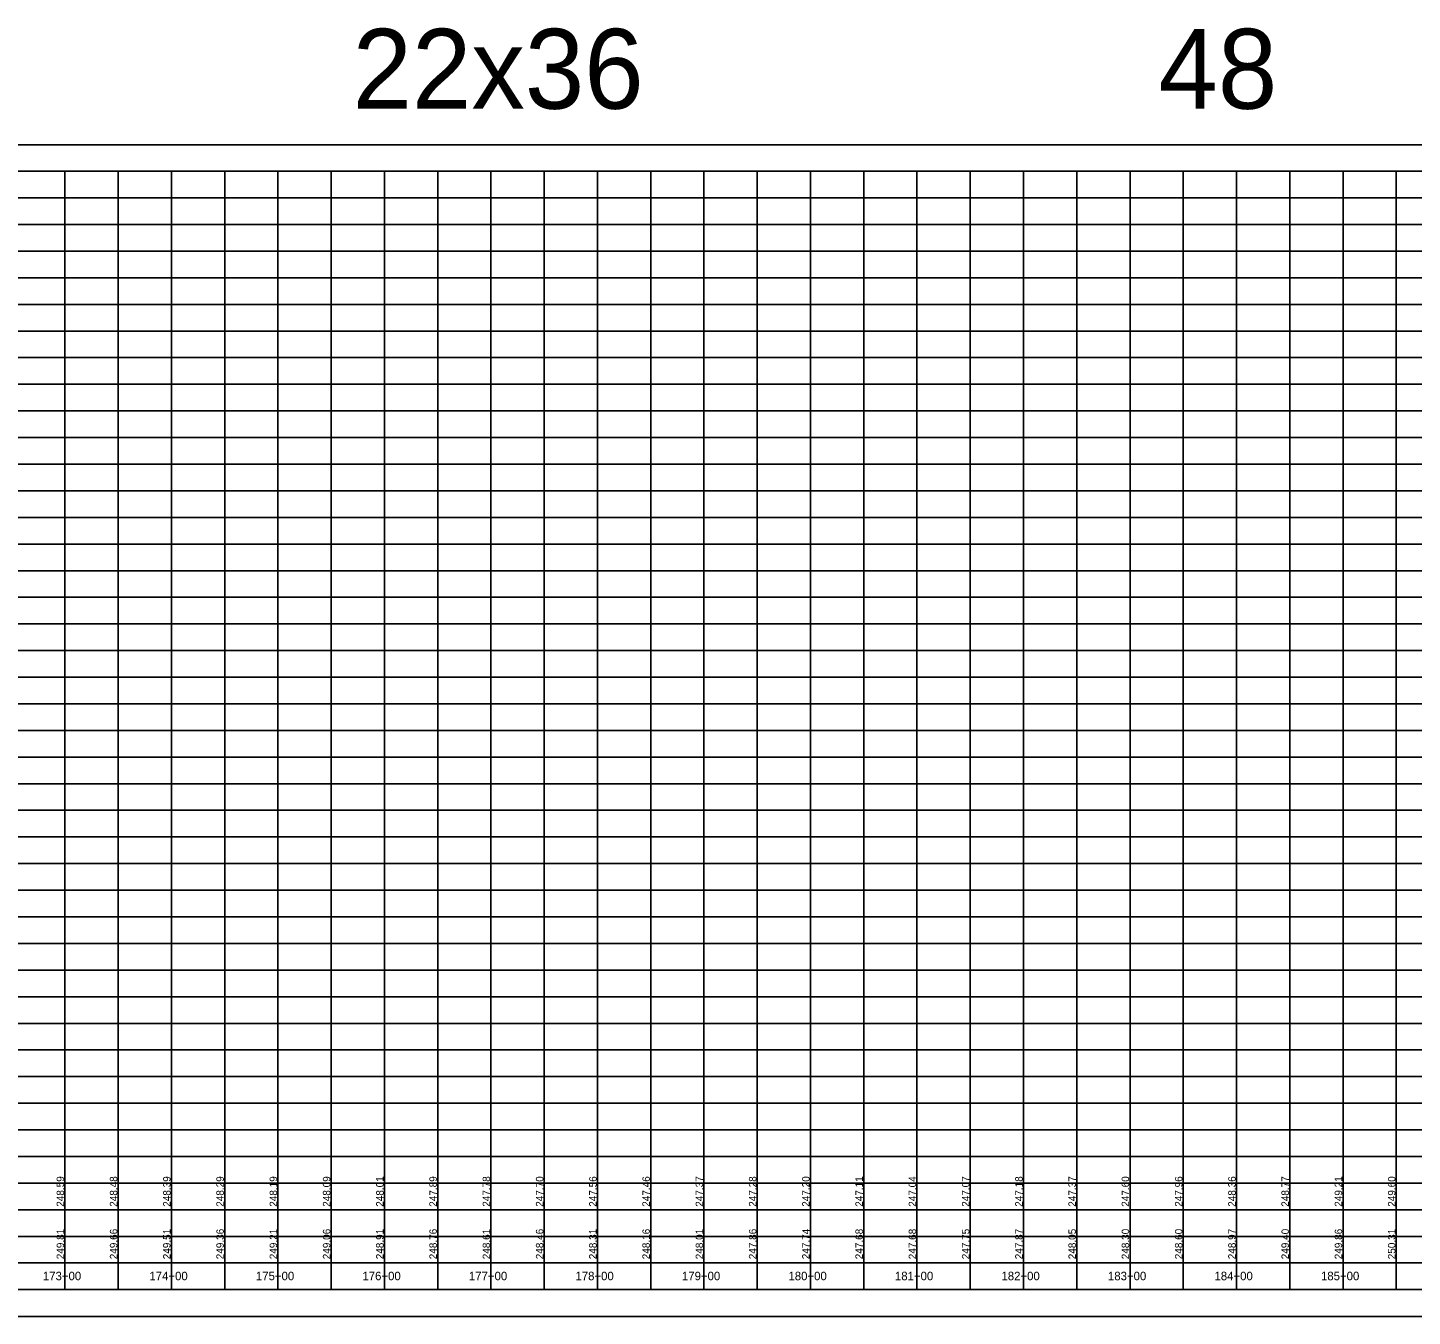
# Model space of a CAD drawing. Extents: x 1873632 to 1926512, y 813126 to 836257.
# Drawn here: x 1895628 to 1896928, y 831005 to 832214 of the extents above; entities that cross this region are included whole.
import ezdxf

# ---------------------------------------------------------------- set-up
doc = ezdxf.new("R2010")
doc.units = 0
for name, color, linetype in [('RD_DDB_StaTX', 7, 'Continuous'), ('RD_DDB_StripGrade', 7, 'Continuous'), ('RD_PD_WallFill', 7, 'Continuous'), ('RD_SHT_IplotShp', 7, 'Continuous')]:
    doc.layers.add(name, color=color, linetype=linetype)

msp = doc.modelspace()

# ---------------------------------------------------------------- linework, layer by layer
at = {"layer": 'RD_PD_WallFill'}
for p, q in [((1894362.9, 832079.6), (1899712.9, 832079.6)), ((1894362.9, 832079.6), (1896112.9, 832079.6)), ((1895662.9, 831029.6), (1895662.9, 832079.6)), ((1895662.9, 831029.6), (1895662.9, 832079.6)), ((1895712.9, 831029.6), (1895712.9, 832079.6)), ((1895712.9, 831029.6), (1895712.9, 832079.6)), ((1895762.9, 831029.6), (1895762.9, 832079.6)), ((1895762.9, 831029.6), (1895762.9, 832079.6)), ((1895812.9, 831029.6), (1895812.9, 832079.6)), ((1895812.9, 831029.6), (1895812.9, 832079.6)), ((1895862.9, 831029.6), (1895862.9, 832079.6)), ((1895862.9, 831029.6), (1895862.9, 832079.6)), ((1895912.9, 831029.6), (1895912.9, 832079.6)), ((1895912.9, 831029.6), (1895912.9, 832079.6)), ((1895962.9, 831029.6), (1895962.9, 832079.6)), ((1895962.9, 831029.6), (1895962.9, 832079.6)), ((1896012.9, 831029.6), (1896012.9, 832079.6)), ((1896012.9, 831029.6), (1896012.9, 832079.6)), ((1896062.9, 831029.6), (1896062.9, 832079.6)), ((1896062.9, 831029.6), (1896062.9, 832079.6)), ((1896112.9, 831029.6), (1896112.9, 832079.6)), ((1896112.9, 831029.6), (1896112.9, 832079.6)), ((1896162.9, 831029.6), (1896162.9, 832079.6)), ((1896162.9, 831029.6), (1896162.9, 832079.6)), ((1896212.9, 831029.6), (1896212.9, 832079.6)), ((1896212.9, 831029.6), (1896212.9, 832079.6)), ((1896262.9, 831029.6), (1896262.9, 832079.6)), ((1896262.9, 831029.6), (1896262.9, 832079.6)), ((1896312.9, 831029.6), (1896312.9, 832079.6)), ((1896312.9, 831029.6), (1896312.9, 832079.6)), ((1896362.9, 831029.6), (1896362.9, 832079.6)), ((1896362.9, 831029.6), (1896362.9, 832079.6)), ((1896412.9, 831029.6), (1896412.9, 832079.6)), ((1896412.9, 831029.6), (1896412.9, 832079.6)), ((1896462.9, 831029.6), (1896462.9, 832079.6)), ((1896462.9, 831029.6), (1896462.9, 832079.6)), ((1896512.9, 831029.6), (1896512.9, 832079.6)), ((1896512.9, 831029.6), (1896512.9, 832079.6)), ((1896562.9, 831029.6), (1896562.9, 832079.6)), ((1896562.9, 831029.6), (1896562.9, 832079.6)), ((1896612.9, 831029.6), (1896612.9, 832079.6)), ((1896612.9, 831029.6), (1896612.9, 832079.6)), ((1896662.9, 831029.6), (1896662.9, 832079.6)), ((1896662.9, 831029.6), (1896662.9, 832079.6)), ((1896712.9, 831029.6), (1896712.9, 832079.6)), ((1896712.9, 831029.6), (1896712.9, 832079.6)), ((1896762.9, 831029.6), (1896762.9, 832079.6)), ((1896762.9, 831029.6), (1896762.9, 832079.6)), ((1896812.9, 831029.6), (1896812.9, 832079.6)), ((1896812.9, 831029.6), (1896812.9, 832079.6)), ((1896862.9, 831029.6), (1896862.9, 832079.6)), ((1896862.9, 831029.6), (1896862.9, 832079.6)), ((1896912.9, 831029.6), (1896912.9, 832079.6)), ((1896912.9, 831029.6), (1896912.9, 832079.6)), ((1894812.9, 832054.6), (1899712.9, 832054.6)), ((1894812.9, 832054.6), (1899712.9, 832054.6)), ((1894812.9, 832029.6), (1899712.9, 832029.6)), ((1894812.9, 832004.6), (1899712.9, 832004.6)), ((1894812.9, 831979.6), (1899712.9, 831979.6)), ((1894812.9, 831954.6), (1899712.9, 831954.6)), ((1894362.9, 831929.6), (1899712.9, 831929.6)), ((1894362.9, 831904.6), (1899712.9, 831904.6)), ((1894362.9, 831879.6), (1899712.9, 831879.6)), ((1894362.9, 831854.6), (1899712.9, 831854.6)), ((1894362.9, 831829.6), (1899712.9, 831829.6)), ((1894362.9, 831804.6), (1899712.9, 831804.6)), ((1894362.9, 831779.6), (1899712.9, 831779.6)), ((1894362.9, 831754.6), (1899712.9, 831754.6)), ((1894362.9, 831729.6), (1899712.9, 831729.6)), ((1894362.9, 831704.6), (1899712.9, 831704.6)), ((1894362.9, 831679.6), (1899712.9, 831679.6)), ((1894362.9, 831654.6), (1899712.9, 831654.6)), ((1894362.9, 831629.6), (1899712.9, 831629.6)), ((1894362.9, 831604.6), (1899712.9, 831604.6)), ((1894362.9, 831579.6), (1899712.9, 831579.6)), ((1894362.9, 831554.6), (1899712.9, 831554.6)), ((1894362.9, 831529.6), (1899712.9, 831529.6)), ((1894362.9, 831504.6), (1899712.9, 831504.6)), ((1894362.9, 831479.6), (1899712.9, 831479.6)), ((1894362.9, 831454.6), (1899712.9, 831454.6)), ((1894362.9, 831429.6), (1899712.9, 831429.6)), ((1894362.9, 831404.6), (1899712.9, 831404.6)), ((1894362.9, 831379.6), (1899712.9, 831379.6)), ((1894362.9, 831354.6), (1899712.9, 831354.6)), ((1894362.9, 831329.6), (1899712.9, 831329.6)), ((1894362.9, 831304.6), (1899712.9, 831304.6)), ((1894362.9, 831279.6), (1899712.9, 831279.6)), ((1894362.9, 831254.6), (1899712.9, 831254.6)), ((1894362.9, 831229.6), (1899712.9, 831229.6)), ((1894362.9, 831204.6), (1899712.9, 831204.6)), ((1894362.9, 831179.6), (1899712.9, 831179.6)), ((1894362.9, 831154.6), (1899712.9, 831154.6)), ((1894362.9, 831129.6), (1899712.9, 831129.6)), ((1894362.9, 831104.6), (1899712.9, 831104.6)), ((1894362.9, 831079.6), (1899712.9, 831079.6)), ((1894362.9, 831054.6), (1899712.9, 831054.6)), ((1894362.9, 831029.6), (1899712.9, 831029.6)), ((1894362.9, 831029.6), (1899712.9, 831029.6))]:
    msp.add_line(p, q, dxfattribs=at)
at = {"layer": 'RD_SHT_IplotShp'}
msp.add_lwpolyline([(1894337.8, 831004.5), (1899737.8, 831004.5), (1899737.8, 832104.5), (1894337.8, 832104.5)], close=True, dxfattribs=at)

# ---------------------------------------------------------------- texts
at = {"layer": 'RD_DDB_StaTX'}
for s, p in [('173+00', (1895642.2, 831038.4)), ('174+00', (1895742.2, 831038.4)), ('175+00', (1895842.2, 831038.4)), ('176+00', (1895942.2, 831038.4)), ('177+00', (1896042.2, 831038.4)), ('178+00', (1896142.2, 831038.4)), ('179+00', (1896242.2, 831038.4)), ('180+00', (1896342.2, 831038.4)), ('181+00', (1896442.2, 831038.4)), ('182+00', (1896542.2, 831038.4)), ('183+00', (1896642.2, 831038.4)), ('184+00', (1896742.2, 831038.4)), ('185+00', (1896842.2, 831038.4))]:
    msp.add_text(s, height=8, dxfattribs=at).set_placement(p)
at = {"layer": 'RD_DDB_StripGrade'}
for s, p in [('248.59', (1895662.1, 831107.4)), ('248.48', (1895712.1, 831107.4)), ('248.39', (1895762.1, 831107.4)), ('248.29', (1895812.1, 831107.4)), ('248.19', (1895862.1, 831107.4)), ('248.09', (1895912.1, 831107.4)), ('248.01', (1895962.1, 831107.4)), ('247.89', (1896012.1, 831107.4)), ('247.78', (1896062.1, 831107.4)), ('247.70', (1896112.1, 831107.4)), ('247.56', (1896162.1, 831107.4)), ('247.46', (1896212.1, 831107.4)), ('247.37', (1896262.1, 831107.4)), ('247.28', (1896312.1, 831107.4)), ('247.20', (1896362.1, 831107.4)), ('247.11', (1896412.1, 831107.4)), ('247.04', (1896462.1, 831107.4)), ('247.07', (1896512.1, 831107.4)), ('247.18', (1896562.1, 831107.4)), ('247.37', (1896612.1, 831107.4)), ('247.60', (1896662.1, 831107.4)), ('247.96', (1896712.1, 831107.4)), ('248.36', (1896762.1, 831107.4)), ('248.77', (1896812.1, 831107.4)), ('249.21', (1896862.1, 831107.4)), ('249.60', (1896912.1, 831107.4)), ('249.81', (1895662.1, 831058.1)), ('249.66', (1895712.1, 831058.1)), ('249.51', (1895762.1, 831058.1)), ('249.36', (1895812.1, 831058.1)), ('249.21', (1895862.1, 831058.1)), ('249.06', (1895912.1, 831058.1)), ('248.91', (1895962.1, 831058.1)), ('248.76', (1896012.1, 831058.1)), ('248.61', (1896062.1, 831058.1)), ('248.46', (1896112.1, 831058.1)), ('248.31', (1896162.1, 831058.1)), ('248.16', (1896212.1, 831058.1)), ('248.01', (1896262.1, 831058.1)), ('247.86', (1896312.1, 831058.1)), ('247.74', (1896362.1, 831058.1)), ('247.68', (1896412.1, 831058.1)), ('247.68', (1896462.1, 831058.1)), ('247.75', (1896512.1, 831058.1)), ('247.87', (1896562.1, 831058.1)), ('248.05', (1896612.1, 831058.1)), ('248.30', (1896662.1, 831058.1)), ('248.60', (1896712.1, 831058.1)), ('248.97', (1896762.1, 831058.1)), ('249.40', (1896812.1, 831058.1)), ('249.86', (1896862.1, 831058.1)), ('250.31', (1896912.1, 831058.1))]:
    msp.add_text(s, height=7, rotation=90, dxfattribs=at).set_placement(p)
at = {"layer": 'RD_PD_WallFill'}
for s, p in [('22x36', (1895933, 832138.3)), ('22x36', (1895933, 832138.3)), ('48', (1896689.6, 832138.3)), ('48', (1896689.6, 832138.3))]:
    msp.add_text(s, height=75, dxfattribs=at).set_placement(p)

doc.saveas('drawing.dxf')
